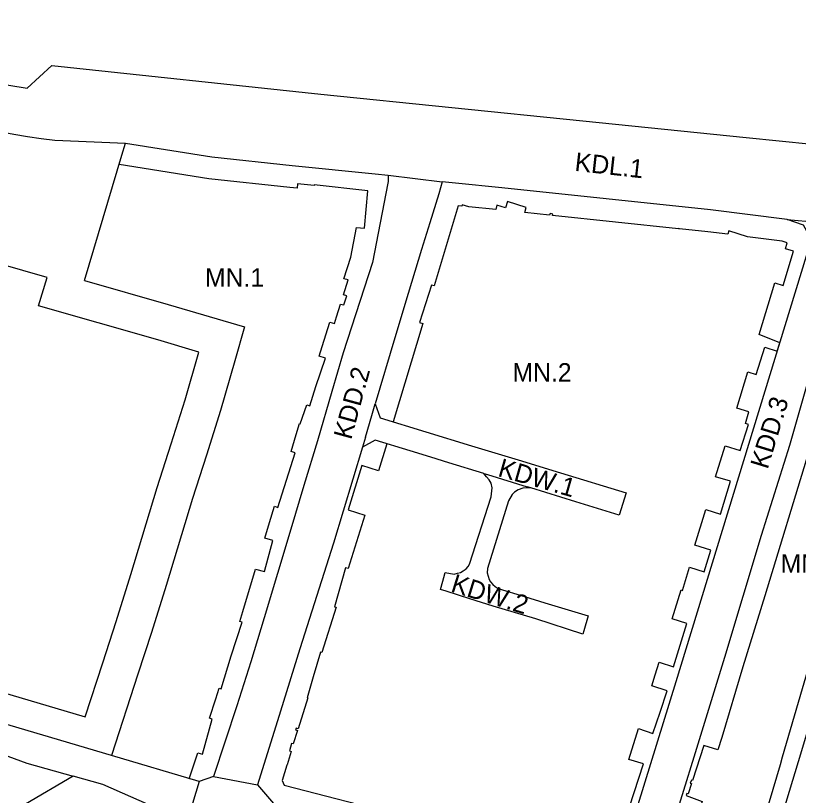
# Model space of a CAD drawing. Extents: x 7419601 to 7420547, y 5548907 to 5549873.
# Drawn here: x 7420033.1 to 7420244.8, y 5549312.7 to 5549523.4 of the extents above; entities that cross this region are included whole.
import ezdxf

# ---------------------------------------------------------------- set-up
doc = ezdxf.new("R2010")
doc.units = 0
for name, color, linetype in [('LIN_linie_rozgraniczajace', 7, 'Continuous'), ('LIN_nieprzekraczalna linia zabudowy', 7, 'Continuous'), ('TXT_opisy_przeznaczen', 7, 'Continuous')]:
    doc.layers.add(name, color=color, linetype=linetype)

msp = doc.modelspace()

# ---------------------------------------------------------------- linework, layer by layer
at = {"layer": 'LIN_linie_rozgraniczajace'}
for p, q in [((7420061.84, 5549485.7), (7420062.82, 5549488.99)), ((7420051.8, 5549451.82), (7420061.84, 5549485.7)), ((7420133.83, 5549480.29), (7420148.48, 5549478.51)), ((7420148.48, 5549478.51), (7420147.54, 5549475.23)), ((7420241.79, 5549468.35), (7420259.85, 5549466.7)), ((7420082.77, 5549316.37), (7420059.02, 5549323.41)), ((7420086.61, 5549317.72), (7420098.57, 5549315.47))]:
    msp.add_line(p, q, dxfattribs=at)
for points in [[(7419989.52, 5549523.43), (7419998.15, 5549516.44), (7420007.04, 5549512.18), (7420016.72, 5549508.44), (7420026.26, 5549505.43), (7420036.29, 5549503.84), (7420042.96, 5549509.97), (7420115.64, 5549502.24), (7420186.48, 5549494.96), (7420230.69, 5549490.47), (7420266.36, 5549486.86), (7420280.44, 5549485.21), (7420290.37, 5549484.05), (7420314.5, 5549481.58), (7420318.73, 5549480.82), (7420355.46, 5549476.76), (7420369.45, 5549475.22), (7420400.67, 5549471.75), (7420403.92, 5549471.39)], [(7419984.5, 5549511.75), (7419993.49, 5549505.39), (7420002.51, 5549498.99), (7420014.32, 5549495.14), (7420021.61, 5549493.48), (7420025.26, 5549492.77), (7420032.62, 5549491.41), (7420036.32, 5549490.76), (7420040.04, 5549490.26), (7420043.75, 5549489.76), (7420062.82, 5549488.99)], [(7420062.82, 5549488.99), (7420086.17, 5549485.26), (7420107.87, 5549482.97), (7420130.34, 5549480.65), (7420133.83, 5549480.29)], [(7420133.83, 5549480.29), (7420133.84, 5549478.63), (7420133.76, 5549478.19), (7420129.61, 5549456.67), (7420121.75, 5549432.27), (7420118.67, 5549421.81), (7420114.74, 5549408.48), (7420111.09, 5549396.43), (7420107.54, 5549384.65), (7420100.31, 5549360.69), (7420096.76, 5549348.8), (7420092.97, 5549336.89), (7420086.61, 5549317.72), (7420082.77, 5549316.37)], [(7420241.79, 5549468.35), (7420221, 5549470.98), (7420164.65, 5549476.88), (7420152.08, 5549478.15), (7420148.48, 5549478.51)], [(7420147.54, 5549475.23), (7420145.13, 5549467.39), (7420142.93, 5549460.25), (7420139.3, 5549448.32), (7420135.68, 5549436.38), (7420130.4, 5549418.5)], [(7420195.45, 5549293.66), (7420198.05, 5549299.11), (7420211.79, 5549343.46), (7420248.32, 5549462.89), (7420246.2, 5549466.76), (7420241.79, 5549468.35)], [(7420206.16, 5549288.67), (7420206.36, 5549290.05), (7420206.43, 5549291.1), (7420208.23, 5549296.04), (7420216.58, 5549323.05), (7420224.94, 5549350.06), (7420234.81, 5549383.04), (7420242.46, 5549407.37), (7420247.93, 5549426.27), (7420253.33, 5549444.88), (7420260.19, 5549466.67)], [(7420051.8, 5549451.82), (7420074.35, 5549445.38), (7420095.07, 5549439.3), (7420092.41, 5549430.08), (7420088.57, 5549416.72), (7420084.74, 5549404.64), (7420081, 5549392.87), (7420073.83, 5549369.43), (7420069.85, 5549356.66), (7420066.19, 5549345.43), (7420059.02, 5549323.41)], [(7420127.71, 5549409.49), (7420129.48, 5549415.38), (7420130.4, 5549418.5)], [(7420130.4, 5549418.5), (7420131.68, 5549414.71)], [(7420131.68, 5549414.71), (7420156.45, 5549407.15), (7420169.04, 5549403.33), (7420180.47, 5549399.85), (7420198.23, 5549394.45), (7420196.34, 5549388.44), (7420184.61, 5549392.04), (7420172.49, 5549395.76), (7420171.46, 5549396.08)], [(7420127.71, 5549409.49), (7420126.91, 5549406.83), (7420119.09, 5549380.8), (7420109.98, 5549352.28), (7420104.74, 5549335.4), (7420098.57, 5549315.47), (7420103.37, 5549309.87)], [(7420159.7, 5549399.69), (7420150.29, 5549402.57), (7420145.37, 5549404.08), (7420139.84, 5549405.77), (7420130.36, 5549408.68), (7420126.91, 5549406.83)], [(7420186.47, 5549356.27), (7420173.82, 5549360.34), (7420168.04, 5549362.07), (7420162.26, 5549363.8), (7420155.92, 5549365.82), (7420149.59, 5549367.85), (7420148.05, 5549368.29), (7420148.2, 5549368.94), (7420148.91, 5549371.59), (7420149.26, 5549372.94), (7420151.71, 5549372.49), (7420152.62, 5549372.69), (7420153.4, 5549372.94), (7420154.19, 5549373.36), (7420154.95, 5549373.92), (7420155.53, 5549374.56), (7420155.89, 5549375.14), (7420161.76, 5549393.32), (7420162.02, 5549395.82), (7420161.7, 5549397.04), (7420161.21, 5549397.95), (7420160.5, 5549398.78), (7420159.7, 5549399.69)], [(7420159.7, 5549399.69), (7420160.74, 5549399.37), (7420171.46, 5549396.08)], [(7420172.49, 5549395.76), (7420171.34, 5549395.82), (7420170.26, 5549395.73), (7420169.02, 5549395.29), (7420168.03, 5549394.66), (7420167.38, 5549393.97), (7420166.39, 5549392.24), (7420160.75, 5549373.96), (7420160.66, 5549372.83), (7420160.88, 5549371.89), (7420161.23, 5549370.99), (7420161.57, 5549370.39), (7420162.17, 5549369.67), (7420162.77, 5549369.14), (7420163.65, 5549368.56), (7420170.74, 5549366.41), (7420176.25, 5549364.73), (7420187.95, 5549361.16), (7420186.74, 5549357.17), (7420186.47, 5549356.27)], [(7420059.02, 5549323.41), (7419903.11, 5549369.61), (7419900.61, 5549370.35), (7419897.16, 5549371.37)], [(7420233.06, 5549283.54), (7420239.1, 5549302.78), (7420244.83, 5549321.8), (7420250.62, 5549340.99), (7420256.57, 5549360.03)], [(7420024.81, 5549325.52), (7420036.14, 5549321.36), (7420048.72, 5549317.81)], [(7420048.72, 5549317.81), (7420035.84, 5549310.28), (7420033.75, 5549308.2), (7420032.79, 5549306.6), (7420032.47, 5549303.85), (7420032.44, 5549294.24), (7420030.96, 5549277.87), (7420028.44, 5549250.88), (7420029.48, 5549227.98), (7420030.53, 5549205.08), (7420033.23, 5549200.31)], [(7420079.46, 5549305.62), (7420056.72, 5549315.6), (7420048.72, 5549317.81)], [(7420082.77, 5549316.37), (7420080.94, 5549310.43), (7420079.46, 5549305.62)]]:
    msp.add_lwpolyline(points, dxfattribs=at)
at = {"layer": 'LIN_nieprzekraczalna linia zabudowy'}
msp.add_line((7420039.34, 5549444.98), (7420041.63, 5549452.68), dxfattribs=at)
for points in [[(7420128.35, 5549476.1), (7420113.84, 5549477.67), (7420113.83, 5549477.55), (7420109.38, 5549477.99), (7420109.26, 5549476.79), (7420107.25, 5549477), (7420085.38, 5549479.31), (7420061.1, 5549483.19)], [(7420080.1, 5549317.16), (7420082.41, 5549324.13), (7420083.65, 5549323.79), (7420086.31, 5549333.29), (7420085.53, 5549333.53), (7420087.26, 5549338.74), (7420088.17, 5549341.61), (7420088.73, 5549341.43), (7420091.46, 5549350.35), (7420094.36, 5549359.45), (7420093.74, 5549359.65), (7420094.56, 5549362.41), (7420098.01, 5549373.84), (7420100.43, 5549373.16), (7420102.71, 5549381.6), (7420100.54, 5549382.22), (7420101.8, 5549386.38), (7420103.13, 5549390.81), (7420104.04, 5549390.52), (7420106.38, 5549397.9), (7420108.75, 5549405.29), (7420107.61, 5549405.65), (7420108.99, 5549410.2), (7420109.87, 5549413.17), (7420110.07, 5549413.1), (7420111.84, 5549418.22), (7420112.66, 5549417.96), (7420114.3, 5549423.18), (7420116.93, 5549430.83), (7420115.24, 5549431.39), (7420116.02, 5549434.04), (7420118.12, 5549440.58), (7420119.35, 5549440.21), (7420119.9, 5549441.99), (7420121.02, 5549445.47), (7420121.89, 5549445.22), (7420122.7, 5549447.66), (7420121.76, 5549447.94), (7420123.06, 5549451.99), (7420121.91, 5549452.33), (7420123.79, 5549458.16), (7420125.33, 5549466.17), (7420127.46, 5549465.97), (7420128.35, 5549476.1)], [(7420041.63, 5549452.68), (7419971.07, 5549472.96), (7419967.82, 5549473.94), (7419966.83, 5549470.09), (7419949, 5549475.18), (7419947.96, 5549471.52)], [(7420152.8, 5549472.04), (7420146.28, 5549450.36), (7420145.56, 5549450.58), (7420142.37, 5549440.47), (7420143.22, 5549440.2), (7420135.23, 5549413.63)], [(7420240.4, 5549462.48), (7420231.05, 5549463.66), (7420225.96, 5549465.26), (7420225.68, 5549464.34), (7420220.31, 5549465.02), (7420212.63, 5549465.82), (7420212.43, 5549465.88), (7420212.42, 5549465.85), (7420178.31, 5549469.42), (7420178.41, 5549469.8), (7420177.66, 5549469.98), (7420177.53, 5549469.5), (7420170.81, 5549470.2), (7420171.21, 5549471.6), (7420166.11, 5549473.16), (7420165.56, 5549471.44), (7420163.29, 5549472.17), (7420162.95, 5549471.02), (7420155.73, 5549471.75), (7420153.92, 5549472.29), (7420153.81, 5549471.94), (7420152.8, 5549472.04)], [(7420234.19, 5549437.2), (7420238.46, 5549451.17), (7420240.7, 5549450.51), (7420243.52, 5549459.74), (7420241.3, 5549460.44), (7420241.78, 5549462), (7420240.4, 5549462.48)], [(7420239.92, 5549321.03), (7420240.53, 5549323.11), (7420251.8, 5549361.56), (7420256.72, 5549381.5), (7420262.37, 5549400.24), (7420268.46, 5549420.4), (7420280.11, 5549458.76)], [(7420051.91, 5549333.86), (7420056.68, 5549348.53), (7420060.32, 5549359.7), (7420064.28, 5549372.38), (7420071.45, 5549395.85), (7420075.21, 5549407.67), (7420079, 5549419.61), (7420082.7, 5549432.51), (7420071.57, 5549435.77), (7420039.34, 5549444.98)], [(7420231.12, 5549427.17), (7420233.38, 5549426.4), (7420235.75, 5549433.78), (7420239.1, 5549432.76), (7420239.8, 5549435.03), (7420234.19, 5549437.2)], [(7420199.09, 5549309.54), (7420202.92, 5549321.17), (7420198.98, 5549322.39), (7420201.56, 5549330.72), (7420205.47, 5549329.38), (7420207.4, 5549335.12), (7420209.35, 5549340.9), (7420205.14, 5549342.27), (7420206.06, 5549345.23), (7420207.11, 5549348.67), (7420211, 5549347.43), (7420214.62, 5549359.11), (7420210.68, 5549360.34), (7420213.08, 5549368.18), (7420213.46, 5549368.06), (7420215.37, 5549374.32), (7420219.34, 5549373.09), (7420221.15, 5549378.96), (7420216.78, 5549380.29), (7420219.74, 5549389.96), (7420223.76, 5549388.7), (7420226.43, 5549397.62), (7420222.43, 5549398.76), (7420225, 5549407.17), (7420229.05, 5549405.89), (7420231.33, 5549412.89), (7420230.49, 5549413.21), (7420231.41, 5549416.31), (7420228.12, 5549417.37), (7420231.12, 5549427.17)], [(7420133.53, 5549407.71), (7420131.26, 5549400.43), (7420126.77, 5549401.86), (7420123.09, 5549389.85), (7420127.52, 5549388.39), (7420123.02, 5549373.95), (7420122.36, 5549374.15), (7420119.36, 5549363.62), (7420119.77, 5549363.51), (7420115.97, 5549351.3), (7420115.6, 5549351.4), (7420113.56, 5549344.69), (7420111.93, 5549339.07), (7420112.15, 5549339.01), (7420109.55, 5549330.67), (7420108.99, 5549330.85), (7420108.82, 5549330.35), (7420109.32, 5549330.19), (7420108.2, 5549326.55), (7420107.73, 5549326.67), (7420107.18, 5549324.71), (7420107.65, 5549324.56), (7420106.52, 5549320.92), (7420106.43, 5549320.87), (7420106.48, 5549320.79), (7420105.2, 5549316.68), (7420105.79, 5549315.41), (7420137.18, 5549307.31)], [(7420247.52, 5549405.31), (7420235.77, 5549366.6), (7420229.82, 5549347.39), (7420224.09, 5549328.34), (7420223.06, 5549324.95), (7420219.23, 5549326.13), (7420216.19, 5549316.67), (7420215.86, 5549316.78), (7420215.52, 5549315.99), (7420215.9, 5549315.85), (7420214.98, 5549313.07), (7420214.64, 5549313.19), (7420214.45, 5549312.63), (7420218.8, 5549311.04), (7420217.16, 5549305.69), (7420216.75, 5549305.81), (7420214.25, 5549297.76), (7420214.69, 5549297.61), (7420212.19, 5549289.43)], [(7419938.72, 5549367.4), (7420051.91, 5549333.86)], [(7420229.23, 5549285.31), (7420231.28, 5549292.04), (7420231.62, 5549291.94), (7420233.48, 5549297.98), (7420235.16, 5549297.43), (7420235.87, 5549299.63), (7420234.28, 5549300.14), (7420234.35, 5549300.38), (7420233.87, 5549300.54), (7420235.01, 5549304.3), (7420239.92, 5549321.03)]]:
    msp.add_lwpolyline(points, dxfattribs=at)

# ---------------------------------------------------------------- texts
at = {"layer": 'TXT_opisy_przeznaczen'}
for s, rotation, p in [('KDL.1', 353.6954, (7420184.16, 5549481.5)), ('KDD.2', 74.7306, (7420123.86, 5549408.6)), ('KDD.3', 73, (7420236.47, 5549400.62)), ('KDW.1', 344.0486, (7420163.29, 5549399.02)), ('KDW.2', 342.7569, (7420150.56, 5549367.83))]:
    msp.add_text(s, height=5, rotation=rotation, dxfattribs=at).set_placement(p)
for s, p in [('MN.1', (7420084.34, 5549450.14)), ('MN.2', (7420167.49, 5549424.5)), ('MN.3', (7420240.01, 5549372.85))]:
    msp.add_text(s, height=5, dxfattribs=at).set_placement(p)

doc.saveas('drawing.dxf')
